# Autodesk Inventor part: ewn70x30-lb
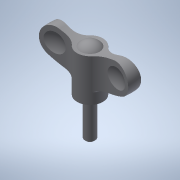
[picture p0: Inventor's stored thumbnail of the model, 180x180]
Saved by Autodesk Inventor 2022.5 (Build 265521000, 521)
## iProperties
Created: 2016-12
Part Number: ewn70x30-lb
Material: 一般
Document SubType Name: Modeling
Designer: imaocorp
Density: 1 g/cm^3
Appearance: 既定
Author: imaocorp
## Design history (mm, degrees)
node "ewn70x30-lb.x_t1"
node "ewn70x30-lb"
node "Base1"
